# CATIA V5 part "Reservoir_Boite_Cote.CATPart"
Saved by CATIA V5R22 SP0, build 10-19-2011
Part number: Reservoir_Boite_Cote
Bounding box of the stored display mesh (mm): x -65.5 to 65.5, y 0 to 5, z -70 to 70
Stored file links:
  D:\PER\CAO_PER_MODIF_2025\CAO_PER_pick&place_2025A\Sous_Ensemble_Boite\Reservoir_Boite\Reservoir_Boite_Cote.CATPart
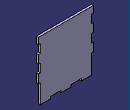
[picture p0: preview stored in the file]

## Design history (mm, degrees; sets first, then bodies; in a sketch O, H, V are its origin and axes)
Body1 (main body)
  Sketch1 on zx-plane, origin (0, 0, 0), H (-1, 0, 0), V (0, 0, 1)
    line L1 (-65.5, 70) -> (65.5, 70)
    line L2 (65.5, 70) -> (65.5, -70)
    line L3 (65.5, -70) -> (-65.5, -70)
    line L4 (-65.5, -70) -> (-65.5, 70)
    length L4 = 140
    length L1 = 131
    horizontal: L1 H, L3 H
    vertical: L2 V, L4 V
    symmetry: L4 L2 V, L1 L3 H
  Pad1: profile Sketch1, direction (0, 1, 0), length 5
  Sketch2 on end face of Pad1, origin (0, 5, 0), H (-1, 0, 0), V (0, 0, 1)
    point P1 (-65.5, -70)
    line L1 (-65.5, -70) -> (-60.5, -70)
    line L2 (-60.5, -70) -> (-60.5, -25)
    line L3 (-60.5, -25) -> (-65.5, -25)
    line L4 (-65.5, -25) -> (-65.5, -70)
    point P2 (-60.5, -70)
    point P3 (-60.5, -25)
    point P4 (-65.5, -25)
    reference projected point E1 (-65.5, -70) from vertex [face of Pad1 from Sketch1.L3 | end face of Pad1 | face of Pad1 from Sketch1.L4]
    point P5 (65.5, -70)
    point P6 (60.5, -70)
    point P7 (60.5, -25)
    point P8 (65.5, -25)
    line L5 (65.5, -70) -> (60.5, -70)
    line L6 (60.5, -70) -> (60.5, -25)
    line L7 (60.5, -25) -> (65.5, -25)
    line L8 (65.5, -25) -> (65.5, -70)
    length L4 = 45
    length L1 = 5
    horizontal: L1 H, L3 H
    vertical: L2 V, L4 V
    coincidence: P1 E1
    symmetry: P1 P5 V, P2 P6 V, P3 P7 V, P4 P8 V, L1 L5 V, L2 L6 V, L3 L7 V, L4 L8 V
  Pocket1: profile Sketch2, direction (0, -1, 0), through (limit type 6)
  Sketch3 on end face of Pad1, origin (0, 5, 0), H (-1, 0, 0), V (0, 0, 1)
    point P1 (-65.5, -5)
    line L1 (-65.5, -5) -> (-60.5, -5)
    line L2 (-60.5, -5) -> (-60.5, 15)
    line L3 (-60.5, 15) -> (-65.5, 15)
    line L4 (-65.5, 15) -> (-65.5, -5)
    point P2 (-60.5, -5)
    point P3 (-60.5, 15)
    point P4 (-65.5, 15)
    reference projected line E1 (-65.5, 70) -> (-65.5, -70) from edge [face of Pad1 from Sketch1.L4 | end face of Pad1]
    reference projected point E2 (-65.5, -25) from vertex [end face of Pad1 | face of Pad1 from Sketch1.L4 | face of Pocket1 from Sketch2.L3]
    point P5 (65.5, -5)
    point P6 (60.5, -5)
    point P7 (60.5, 15)
    point P8 (65.5, 15)
    line L5 (65.5, -5) -> (60.5, -5)
    line L6 (60.5, -5) -> (60.5, 15)
    line L7 (60.5, 15) -> (65.5, 15)
    line L8 (65.5, 15) -> (65.5, -5)
    distance P1 E2 = 20
    length L4 = 20
    length L3 = 5
    horizontal: L1 H, L3 H
    vertical: L2 V, L4 V
    coincidence: L4 E1
    symmetry: P1 P5 V, P2 P6 V, P3 P7 V, P4 P8 V, L1 L5 V, L2 L6 V, L3 L7 V, L4 L8 V
  Pocket2: profile Sketch3, direction (0, -1, 0), through (limit type 6)
  RectPattern1: of Pocket2, direction 1 instances 2, spacing 40, along edge [face of Pad1 from Sketch1.L4 | end face of Pad1] reversed
  Sketch4 on end face of Pad1, origin (0, 5, 0), H (-1, 0, 0), V (0, 0, 1)
    axis line L1 (0, 0) -> (0, -125.2345)
    point P2 (12, -70)
    line L2 (12, -70) -> (12, -65)
    point P3 (12, -65)
    line L3 (12, -65) -> (36, -65)
    point P4 (36, -65)
    line L4 (36, -65) -> (36, -70)
    point P5 (36, -70)
    line L5 (36, -70) -> (12, -70)
    reference projected line E1 (-65.5, -70) -> (65.5, -70) from edge [face of Pad1 from Sketch1.L3 | end face of Pad1]
    reference projected line E2 (-65.5, -70) -> (65.5, -70) from edge [face of Pad1 from Sketch1.L3 | end face of Pad1]
    point P6 (-12, -70)
    point P7 (-12, -65)
    point P8 (-36, -65)
    point P9 (-36, -70)
    line L6 (-12, -70) -> (-12, -65)
    line L7 (-12, -65) -> (-36, -65)
    line L8 (-36, -65) -> (-36, -70)
    line L9 (-36, -70) -> (-12, -70)
    distance L4 L2 = 24
    distance L2 L1 = 12
    distance L3 E1 = 5
    vertical: L1 V, L2 V, L4 V
    horizontal: L3 H, L5 H
    coincidence: L5 E2
    symmetry: P2 P6 L1, P3 P7 L1, P4 P8 L1, P5 P9 L1, L2 L6 L1, L3 L7 L1, L4 L8 L1, L5 L9 L1
  Pocket3: profile Sketch4, direction (0, -1, 0), through (limit type 6)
